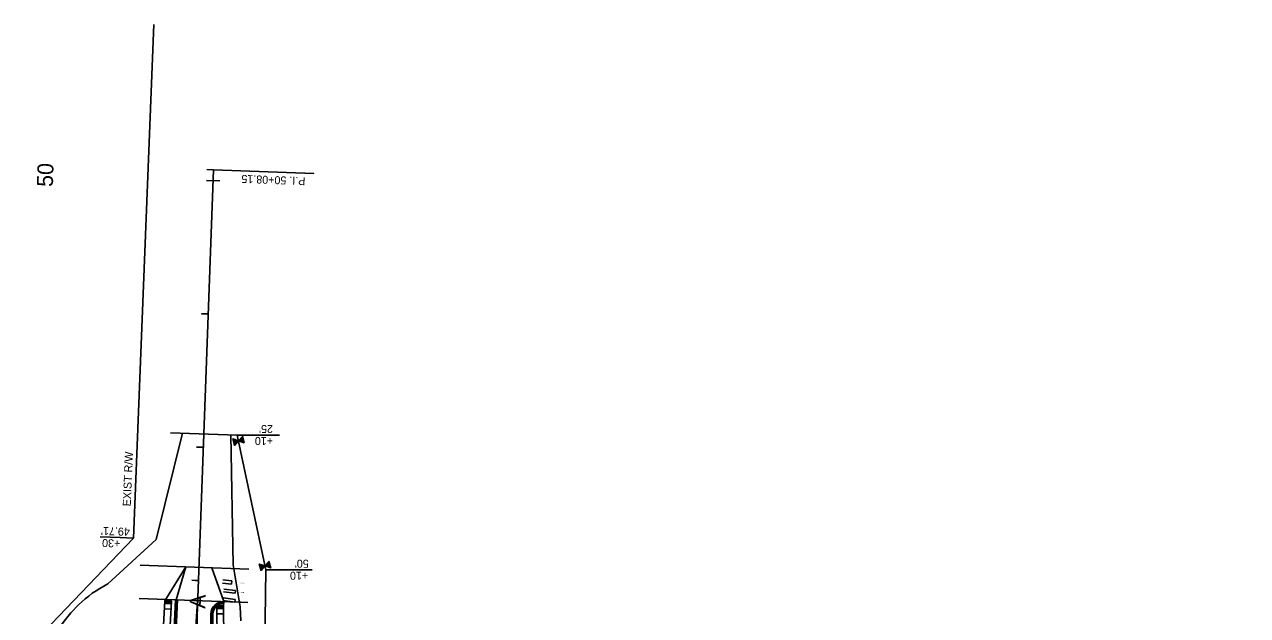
# Model space of a CAD drawing. Extents: x 670017 to 673226, y 705371 to 707498.
# Drawn here: x 671617 to 672533, y 707055 to 707498 of the extents above; entities that cross this region are included whole.
import ezdxf

# ---------------------------------------------------------------- set-up
doc = ezdxf.new("R2010")
doc.units = 0
for name, color, linetype in [('EL L SCBV', 7, 'Continuous'), ('EL R SCBV', 7, 'Continuous'), ('R_Drainage Stage 1', 7, 'Continuous'), ('R_Drainage Stage 2A', 7, 'Continuous'), ('R_Fence', 7, 'Continuous'), ('R_Horz Alg', 7, 'Continuous'), ('R_Horz Alg Station', 7, 'Continuous'), ('R_Horz Alg Station Annot', 7, 'Continuous'), ('R_No Plot', 7, 'Continuous'), ('R_No Plot FOC', 7, 'Continuous'), ('R_Proposed Const Limits', 7, 'Continuous'), ('R_Proposed Const Limits Stage 1A', 7, 'Continuous'), ('R_Proposed Road', 7, 'Continuous'), ('R_Proposed Road Stage 1A', 7, 'Continuous'), ('R_Proposed Sidewalk Stage 1', 7, 'Continuous'), ('R_Proposed Sidewalk Stage 1A', 7, 'Continuous'), ('R_ROW', 7, 'Continuous'), ('R_ROW Annot', 7, 'Continuous'), ('R_Striping', 7, 'Continuous'), ('S_EXIST_ROW', 7, 'Continuous')]:
    doc.layers.add(name, color=color, linetype=linetype)

msp = doc.modelspace()

# ---------------------------------------------------------------- linework, layer by layer
at = {"layer": 'EL L SCBV'}
msp.add_line((671731.31, 707067.02), (671724.66, 706939.18), dxfattribs=at)
at = {"layer": 'EL R SCBV'}
msp.add_line((671756.2, 707056.32), (671757.13, 706900.72), dxfattribs=at)
msp.add_arc((671765.7, 707056.23), 9.5, 87.86573, 179.50026, dxfattribs=at)
at = {"layer": 'R_Drainage Stage 1'}
for p, q in [((671765.06, 707079.45), (671771.77, 707078.84)), ((671765.29, 707081.94), (671771.87, 707081.34)), ((671766.05, 707075.06), (671774.6, 707074.01)), ((671765.25, 707066.56), (671774.27, 707065.2)), ((671765.71, 707068.5), (671774.34, 707067.2)), ((671765.72, 707073.09), (671774.52, 707072))]:
    msp.add_line(p, q, dxfattribs=at)
at = {"layer": 'R_Drainage Stage 2A'}
for p, q in [((671771.87, 707081.34), (671771.77, 707078.84)), ((671774.34, 707067.2), (671774.27, 707065.2)), ((671774.6, 707074.01), (671774.52, 707072))]:
    msp.add_line(p, q, dxfattribs=at)
at = {"layer": 'R_Fence'}
for p, q in [((671776.25, 707185.49), (671772.58, 707187.6)), ((671775.91, 707185.11), (671772.76, 707186.92)), ((671775.58, 707184.72), (671772.95, 707186.23)), ((671775.24, 707184.34), (671773.13, 707185.55)), ((671774.91, 707183.96), (671773.32, 707184.87)), ((671774.57, 707183.57), (671773.5, 707184.19)), ((671776.59, 707185.88), (671774.95, 707186.81)), ((671777.37, 707186), (671776.92, 707186.26)), ((671779.79, 707185.19), (671777.26, 707186.64)), ((671781.04, 707185.05), (671777.59, 707187.03)), ((671780.85, 707185.73), (671777.93, 707187.41)), ((671780.67, 707186.41), (671778.26, 707187.79)), ((671780.48, 707187.1), (671778.6, 707188.18)), ((671780.3, 707187.78), (671778.94, 707188.56)), ((671780.12, 707188.46), (671779.27, 707188.95)), ((671779.93, 707189.14), (671779.61, 707189.33)), ((671774.24, 707183.19), (671773.69, 707183.5)), ((671773.9, 707182.8), (671773.87, 707182.82)), ((671796.2, 707091.71), (671792.53, 707093.82)), ((671795.86, 707091.32), (671792.71, 707093.13)), ((671795.53, 707090.94), (671792.9, 707092.45)), ((671796.53, 707092.09), (671794.9, 707093.03)), ((671797.32, 707092.22), (671796.87, 707092.48)), ((671799.74, 707091.41), (671797.21, 707092.86)), ((671800.99, 707091.26), (671797.54, 707093.24)), ((671800.8, 707091.95), (671797.88, 707093.63)), ((671800.62, 707092.63), (671798.21, 707094.01)), ((671800.43, 707093.31), (671798.55, 707094.39)), ((671800.25, 707094), (671798.88, 707094.78)), ((671800.06, 707094.68), (671799.22, 707095.16)), ((671799.88, 707095.36), (671799.55, 707095.55)), ((671795.19, 707090.56), (671793.08, 707091.77)), ((671794.86, 707090.17), (671793.27, 707091.09)), ((671794.52, 707089.79), (671793.45, 707090.4)), ((671794.18, 707089.41), (671793.63, 707089.72)), ((671793.85, 707089.02), (671793.82, 707089.04))]:
    msp.add_line(p, q, dxfattribs=at)
for points in [[(671776.84, 707186.17), (671776.86, 707186.17), (671781.12, 707184.74), (671779.82, 707189.57), (671776.85, 707186.18), (671776.84, 707186.18), (671772.58, 707187.61), (671773.88, 707182.78), (671776.84, 707186.17)], [(671796.79, 707092.39), (671796.81, 707092.39), (671801.07, 707090.96), (671799.76, 707095.79), (671796.8, 707092.4), (671796.79, 707092.4), (671792.52, 707093.83), (671793.83, 707089), (671796.79, 707092.39)]]:
    msp.add_lwpolyline(points, dxfattribs=at)
at = {"layer": 'R_Horz Alg'}
msp.add_line((671726.73, 706541.35), (671758.33, 707389.39), dxfattribs=at)
at = {"layer": 'R_Horz Alg Station'}
for points in [[(671753.33, 707389.58), (671763.33, 707389.2)], [(671758.33, 707389.39), (671833.28, 707386.6), (671827.28, 707386.82)], [(671753.03, 707381.43), (671763.02, 707381.06)], [(671753.03, 707381.43), (671763.02, 707381.06)], [(671749.31, 707281.5), (671754.3, 707281.31)], [(671751.8, 707281.41), (671754.3, 707281.31)], [(671745.58, 707181.57), (671750.58, 707181.38)], [(671748.08, 707181.48), (671750.58, 707181.38)], [(671741.86, 707081.64), (671746.85, 707081.45)], [(671744.36, 707081.54), (671746.85, 707081.45)]]:
    msp.add_lwpolyline(points, dxfattribs=at)
at = {"layer": 'R_No Plot'}
msp.add_line((671775.93, 707190.44), (671797.39, 707089.58), dxfattribs=at)
for points in [[(671725.97, 707192.31), (671775.93, 707190.44)], [(671703.34, 707093.08), (671784.75, 707090.05)], [(672600.73, 706535.93), (672600.73, 706535.93), (672146.36, 706559.78), (671852.81, 706595.21), (671791.92, 706679.49), (671797.39, 707089.58)], [(671702.41, 707068.1), (671783.82, 707065.06)]]:
    msp.add_lwpolyline(points, dxfattribs=at)
at = {"layer": 'R_No Plot FOC'}
for p, q in [((671723.66, 706939.23), (671730.31, 707067.07)), ((671758.13, 706900.73), (671757.2, 707056.32))]:
    msp.add_line(p, q, dxfattribs=at)
msp.add_arc((671765.7, 707056.23), 8.5, 87.86573, 179.50026, dxfattribs=at)
at = {"layer": 'R_Proposed Const Limits'}
msp.add_line((671772.97, 707093.15), (671771.32, 707190.62), dxfattribs=at)
msp.add_lwpolyline([(671778.79, 707051.22), (671778.13, 707061.87), (671772.97, 707093.15)], dxfattribs=at)
at = {"layer": 'R_Proposed Const Limits Stage 1A'}
msp.add_lwpolyline([(671678.93, 707078.93), (671715.26, 707112.31), (671735, 707191.97)], dxfattribs=at)
for centre, radius, start, end in [((671721.07, 706996.94), 92.19, 117.20421, 134.01947), ((671736.94, 706981.8), 114.1, 134.4692, 198.3972)]:
    msp.add_arc(centre, radius, start, end, dxfattribs=at)
at = {"layer": 'R_Proposed Road'}
for p, q in [((671766.06, 707065.73), (671756.98, 707091.08)), ((671766, 707064.23), (671766.06, 707065.73)), ((671757.13, 706900.72), (671756.2, 707056.32)), ((671758.63, 706900.73), (671757.7, 707056.32))]:
    msp.add_line(p, q, dxfattribs=at)
for radius in [9.5, 8]:
    msp.add_arc((671765.7, 707056.23), radius, 87.86573, 179.50026, dxfattribs=at)
at = {"layer": 'R_Proposed Road Stage 1A'}
for p, q in [((671730.31, 707067.06), (671737.54, 707091.81)), ((671723.17, 706939.26), (671729.81, 707067.1)), ((671724.66, 706939.18), (671731.31, 707067.02)), ((671731.31, 707067.02), (671729.81, 707067.1))]:
    msp.add_line(p, q, dxfattribs=at)
at = {"layer": 'R_Proposed Sidewalk Stage 1'}
for p, q in [((671766.63, 706900.57), (671765.65, 707065.73)), ((671761.63, 706900.65), (671760.66, 707064.28)), ((671765.68, 707060.48), (671760.68, 707060.45)), ((671765.7, 707056.48), (671760.7, 707056.45))]:
    msp.add_line(p, q, dxfattribs=at)
msp.add_lwpolyline([(671760.67, 707062.45), (671765.67, 707062.48), (671765.68, 707060.48), (671760.68, 707060.45)], close=True, dxfattribs=at)
for centre in [(671761.07, 707062.05), (671761.07, 707061.45), (671761.08, 707060.85), (671761.67, 707062.05), (671761.67, 707061.45), (671761.68, 707060.85), (671762.27, 707062.06), (671762.27, 707061.46), (671762.28, 707060.86), (671762.87, 707062.06), (671762.87, 707061.46), (671762.88, 707060.86), (671763.47, 707062.06), (671763.47, 707061.46), (671763.48, 707060.86), (671764.07, 707062.07), (671764.07, 707061.47), (671764.08, 707060.87), (671764.67, 707062.07), (671764.67, 707061.47), (671764.68, 707060.87), (671765.27, 707062.08), (671765.27, 707061.48), (671765.28, 707060.88)]:
    msp.add_circle(centre, 0.165, dxfattribs=at)
at = {"layer": 'R_Proposed Sidewalk Stage 1A'}
for p, q in [((671721.75, 707066.16), (671737.54, 707091.81)), ((671715.18, 706939.75), (671721.75, 707066.16)), ((671720.17, 706939.45), (671726.74, 707065.9)), ((671726.43, 707059.91), (671721.44, 707060.17)), ((671726.64, 707063.9), (671721.64, 707064.16))]:
    msp.add_line(p, q, dxfattribs=at)
msp.add_lwpolyline([(671721.75, 707066.16), (671726.74, 707065.9), (671726.64, 707063.9), (671721.64, 707064.16)], close=True, dxfattribs=at)
for centre in [(671722.1, 707065.14), (671722.13, 707065.74), (671722.69, 707065.11), (671722.73, 707065.71), (671723.29, 707065.08), (671723.32, 707065.68), (671723.89, 707065.05), (671723.92, 707065.65), (671724.49, 707065.02), (671724.52, 707065.62), (671725.09, 707064.99), (671725.12, 707065.59), (671725.69, 707064.96), (671725.72, 707065.55), (671726.29, 707064.92), (671726.32, 707065.52), (671722.06, 707064.54), (671722.66, 707064.51), (671723.26, 707064.48), (671723.86, 707064.45), (671724.46, 707064.42), (671725.06, 707064.39), (671725.66, 707064.36), (671726.26, 707064.32)]:
    msp.add_circle(centre, 0.165, dxfattribs=at)
at = {"layer": 'R_ROW'}
msp.add_line((671775.93, 707190.44), (671797.39, 707089.58), dxfattribs=at)
for points in [[(671688.75, 706863.46), (671616.54, 706941.21), (671619.89, 707031.15), (671698.29, 707113.28)], [(672600.73, 706535.93), (672600.73, 706535.93), (672146.36, 706559.78), (671852.81, 706595.21), (671791.92, 706679.49), (671797.39, 707089.58)]]:
    msp.add_lwpolyline(points, dxfattribs=at)
at = {"layer": 'R_ROW Annot'}
for points in [[(671775.93, 707190.44), (671787.67, 707190.56), (671807.67, 707190.56)], [(671698.29, 707113.28), (671688.3, 707113.65), (671673.31, 707114.21)], [(671797.19, 707089.58), (671812.19, 707089.58), (671832.19, 707089.58)]]:
    msp.add_lwpolyline(points, dxfattribs=at)
at = {"layer": 'R_Striping'}
for p in [(671736.27, 706901.3), (671743.14, 706901.24)]:
    msp.add_line(p, (671746.29, 707066.46), dxfattribs=at)
at = {"layer": 'S_EXIST_ROW'}
msp.add_lwpolyline([(671698.29, 707113.28), (671702.02, 707208.02), (671713.44, 707498.37)], dxfattribs=at)

# ---------------------------------------------------------------- texts
at = {"layer": 'R_Horz Alg'}
msp.add_text('A', height=12, rotation=87.86573, dxfattribs=at).set_placement((671752.07, 707060.24))
at = {"layer": 'R_Horz Alg Station Annot'}
for s, height, rotation, p in [('50', 12, 87.86573, (671637.76, 707376.41)), ('P.I. 50+08.15', 6, 177.86573, (671827.17, 707383.82))]:
    msp.add_text(s, height=height, rotation=rotation, dxfattribs=at).set_placement(p)
at = {"layer": 'R_No Plot'}
for s, p in [(' 46+99.25 ', (671777.79, 707079.25)), (' 46+85.44 ', (671777.28, 707065.45)), (' 46+92.33 ', (671777.54, 707072.34))]:
    msp.add_text(s, height=0.6, rotation=357.86573, dxfattribs=at).set_placement(p)
at = {"layer": 'R_ROW Annot'}
for s, rotation, p in [("25'", 180, (671802.75, 707198.06)), ('+10', 180, (671802.81, 707189.06)), ('EXIST R/W', 87.62733, (671696.17, 707137.02)), ("49.71'", 177.86573, (671695.6, 707120.89)), ('+30', 177.86573, (671688.42, 707112.15)), ("50'", 180, (671829.55, 707097.08)), ('+10', 180, (671829.13, 707088.08))]:
    msp.add_text(s, height=6, rotation=rotation, dxfattribs=at).set_placement(p)

doc.saveas('drawing.dxf')
